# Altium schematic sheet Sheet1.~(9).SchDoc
size A4; SheetNumber: 1; SheetTotal: 1
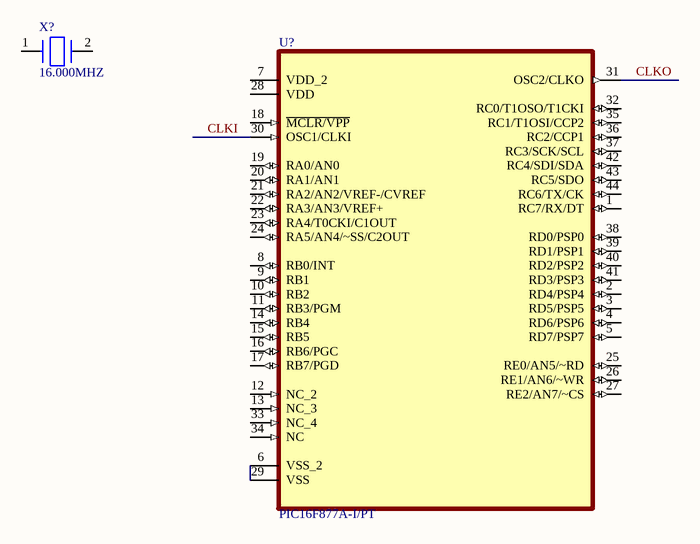
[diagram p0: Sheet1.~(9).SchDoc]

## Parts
U?  PIC16F877A-I/PT  [TQFP-44]
X?  16.000MHZ  [FP-ABM7-MFG]

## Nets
CLKI: U?.30(OSC1/CLKI)
CLKO: U?.31(OSC2/CLKO)
NetU?_6: U?.6(VSS_2) U?.29(VSS)

Not connected (* = marked no-connect by the designer): U? 1(RC7/RX/DT) 2(RD4/PSP4) 3(RD5/PSP5) 4(RD6/PSP6) 5(RD7/PSP7) 7(VDD_2) 8(RB0/INT) 9(RB1) 10(RB2) 11(RB3/PGM) 12(NC_2) 13(NC_3) 14(RB4) 15(RB5) 16(RB6/PGC) 17(RB7/PGD) 18(~{MCLR/VPP}) 19(RA0/AN0) 20(RA1/AN1) 21(RA2/AN2/VREF-/CVREF) 22(RA3/AN3/VREF+) 23(RA4/T0CKI/C1OUT) 24(RA5/AN4/~SS/C2OUT) 25(RE0/AN5/~RD) 26(RE1/AN6/~WR) 27(RE2/AN7/~CS) 28(VDD) 32(RC0/T1OSO/T1CKI) 33(NC_4) 34(NC) 35(RC1/T1OSI/CCP2) 36(RC2/CCP1) 37(RC3/SCK/SCL) 38(RD0/PSP0) 39(RD1/PSP1) 40(RD2/PSP2) 41(RD3/PSP3) 42(RC4/SDI/SDA) 43(RC5/SDO) 44(RC6/TX/CK); X? 1 2

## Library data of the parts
U? = PIC16F877A-I/PT: PIC16F877A Microcontroller IC 8-Bit 20MHz 14KB _8K x 14_ FLASH 44-TQFP _10x10_; MF: Microchip
X? = ABM7-16.000MHZ-4-T: Crystal 16MHz ±30ppm (Tol) ±50ppm (Stability) 18pF FUND 50Ohm 2-Pin Mini-CSMD T/R; Manufacturer: Abracon; ESR (Equivalent Series Resistance): 50R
